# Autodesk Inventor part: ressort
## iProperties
Shininess: 20.0
Length Units: 11269
Angle Units: 11279
Time Units: 11290
Mass Units: 11283
Length Display Precision: 3
Angle Display Precision: 2
Created: 2001-12
Part Number: ressort
Material: Par défaut
Document SubType Name: Modélisation
Designer: PROSTDA
Density: 0.0
Volumn: 0.0
Area: 0.0
PropertySet Name: Model Information
Control State: 0
Master: False
Checked Out: False
Author: PROSTDA
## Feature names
1. Hélicoïde1
